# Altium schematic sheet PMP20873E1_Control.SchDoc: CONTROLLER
size 431 x 279 mm; Date: Not shown in title block; ApprovedBy: Not shown in title block; CheckedBy: Not shown in title block; Author: Not shown in title block; CompanyName: Not shown in title block; DrawnBy: Eric Faraci; Engineer: Not shown in title block; Organization: Not shown in title block; Address1: Not shown in title block; Address2: Not shown in title block; Address3: Not shown in title block; Address4: Not shown in title block; DocumentNumber: 3; Revision: Use project parameter SCH_Rev; SheetNumber: 3; SheetTotal: 8; PageSetup: Record=PageOptions¦CenterHorizontal=True¦CenterVertical=True¦PrintScale=0.96¦XCorrection=1.00¦YCorrection=1.00¦PrintKind=0¦BorderSize=5000000¦LeftOffset=0¦BottomOffset=0¦Orientation=2¦PaperLength=1000¦PaperWidth=1000¦Scale=100¦PaperSource=15¦PrintQuality=600¦MediaType=1¦DitherType=10¦PaperKind=11x17¦PrintScaleMode=1
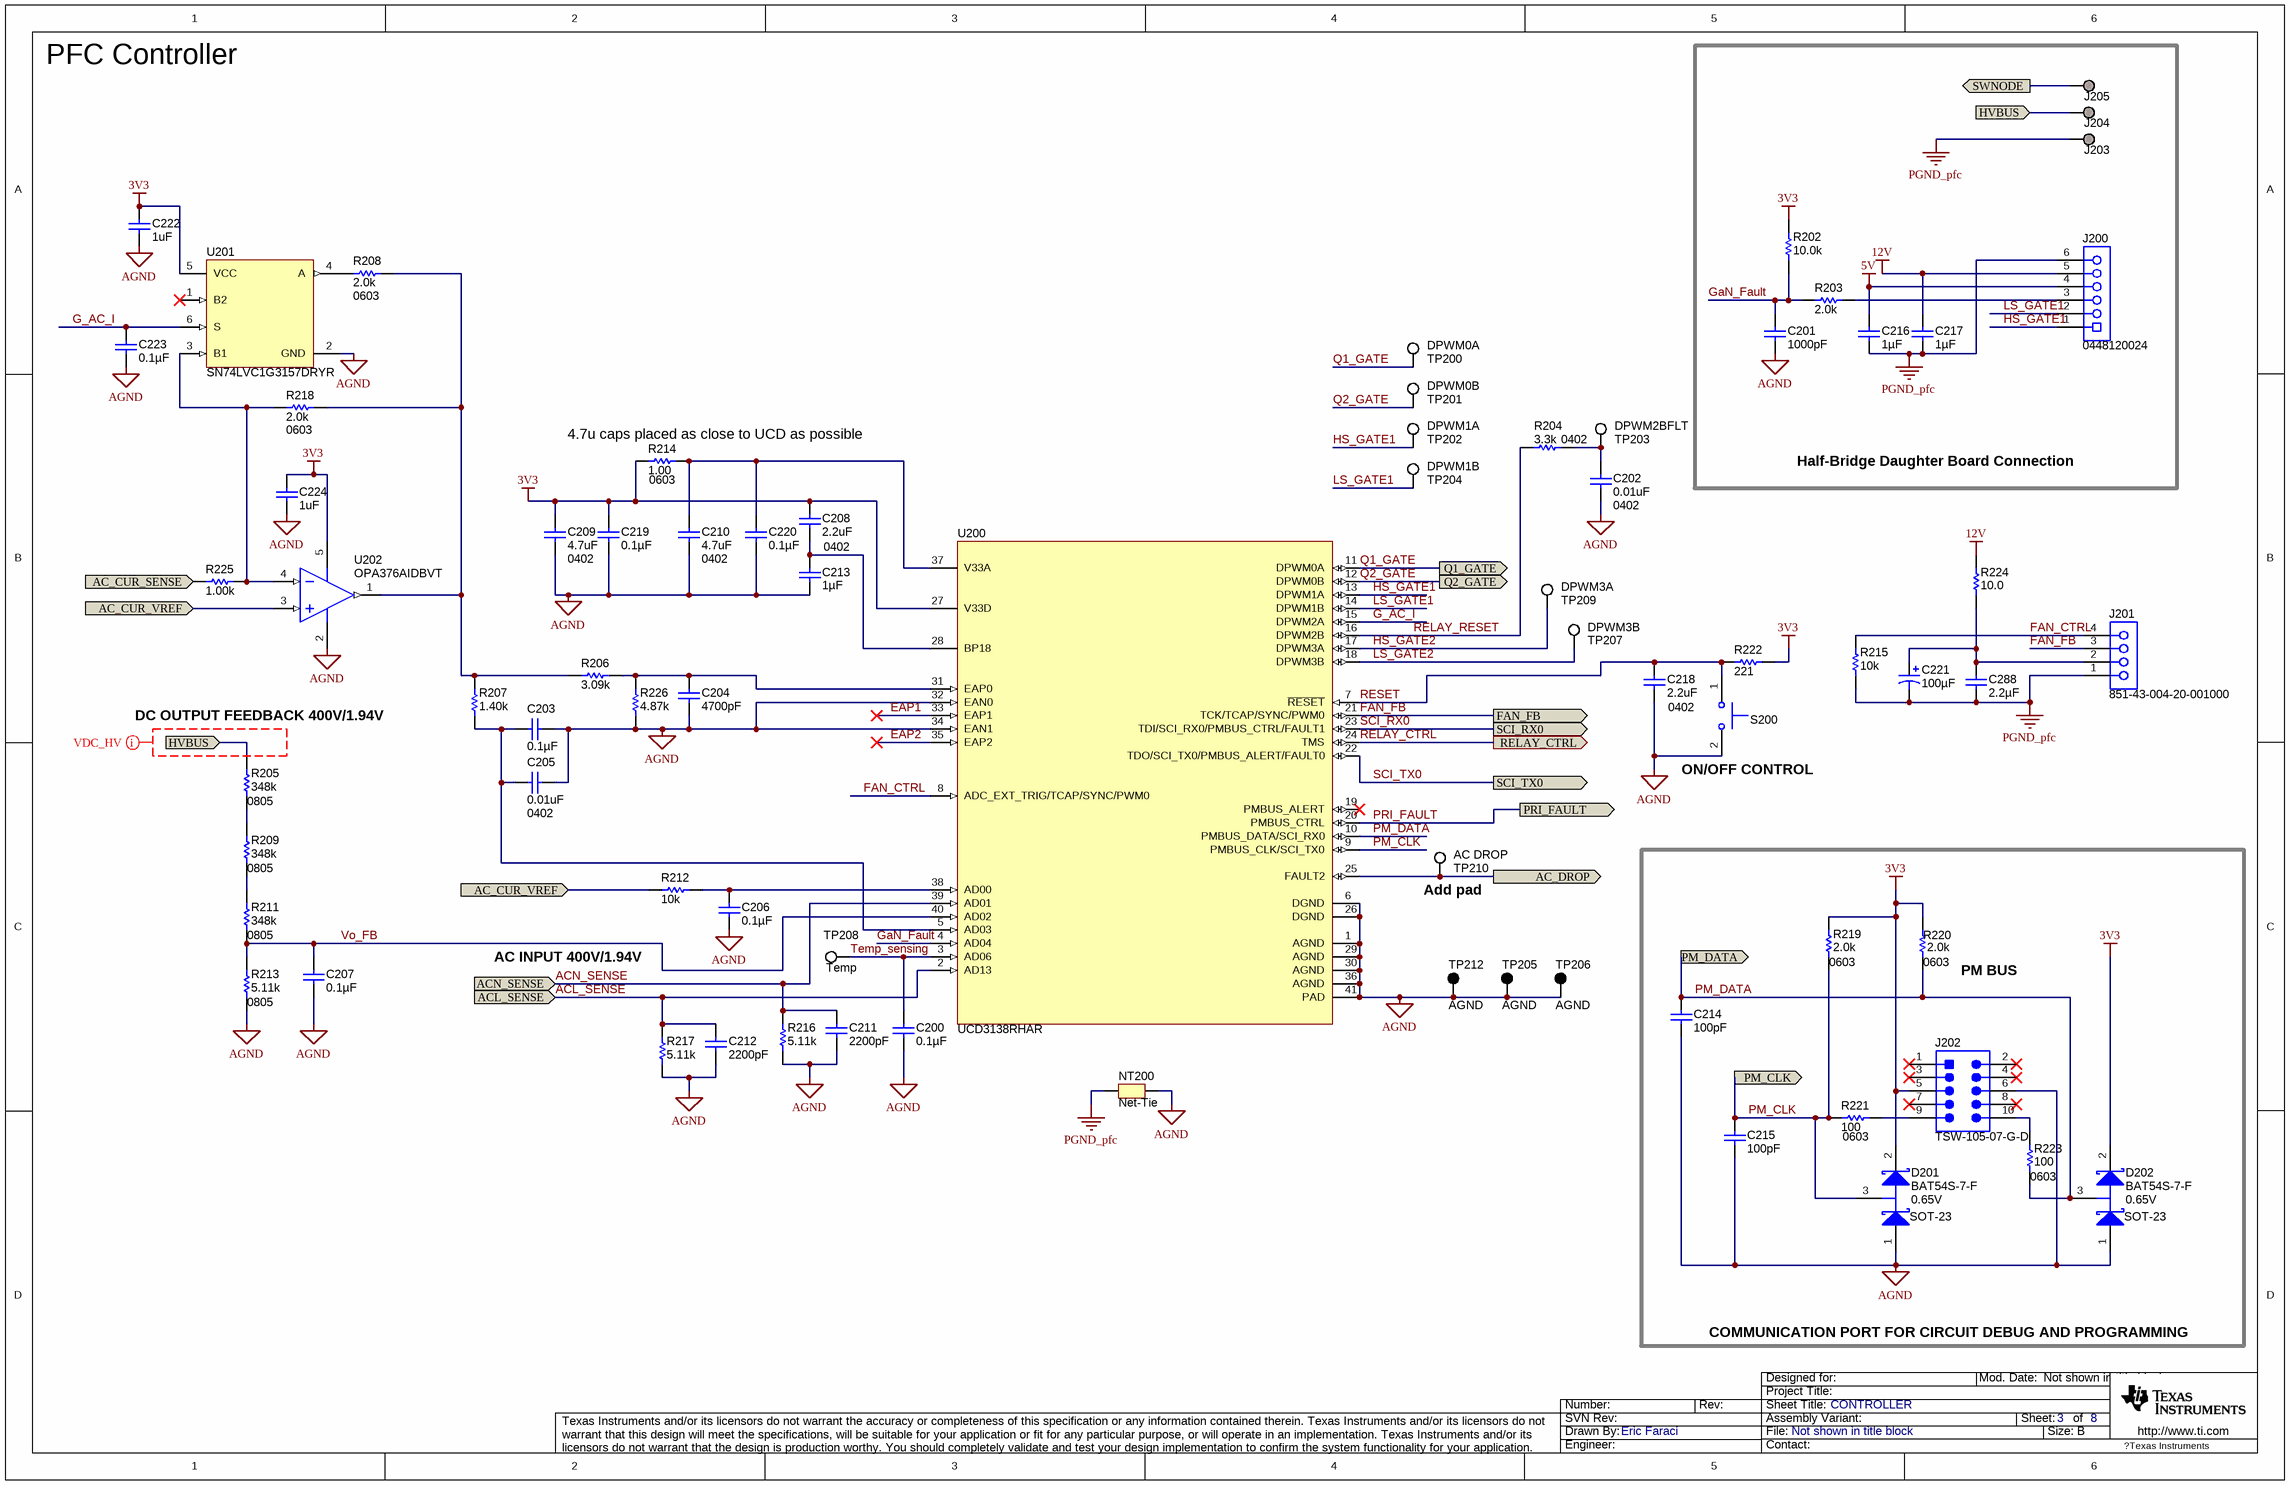
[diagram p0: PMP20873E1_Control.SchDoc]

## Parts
C200  ValueDisplayed: 0.1µF  [0402]  (hidden comment: GRM155R60J104KA01D)
C201  ValueDisplayed: 1000pF  [0402]  (hidden comment: GRM155R61A102KA01D)
C202  ValueDisplayed: 0.01uF  [0402]  (hidden comment: GRM155R70J103KA01D)
C203  ValueDisplayed: 0.1µF  [0402]  (hidden comment: GRM155R60J104KA01D)
C204  ValueDisplayed: 4700pF  [0402]  (hidden comment: GRM155R60J472KA01D)
C205  ValueDisplayed: 0.01uF  [0402]  (hidden comment: GRM155R70J103KA01D)
C206  ValueDisplayed: 0.1µF  [0402]  (hidden comment: GRM155R60J104KA01D)
C207  ValueDisplayed: 0.1µF  [0603]  (hidden comment: GCM188R71H104KA57D)
C208  ValueDisplayed: 2.2uF  [0402]  (hidden comment: C1005X5R1A225K050BC)
C209  value 4.7uF  [0402]  (hidden comment: CL05A475MQ5NRNC)
C210  value 4.7uF  [0402]  (hidden comment: CL05A475MQ5NRNC)
C211  ValueDisplayed: 2200pF  [0603]  (hidden comment: C1608X7R1H222K)
C212  ValueDisplayed: 2200pF  [0603]  (hidden comment: C1608X7R1H222K)
C213  ValueDisplayed: 1µF  [0402]  (hidden comment: GRM155R61A105KE15D)
C214  ValueDisplayed: 100pF  [0402]  (hidden comment: GRM1555C1H101JA01D)
C215  ValueDisplayed: 100pF  [0402]  (hidden comment: GRM1555C1H101JA01D)
C216  ValueDisplayed: 1µF  [0603]  (hidden comment: C1608X7R1E105K080AB)
C217  ValueDisplayed: 1µF  [0603]  (hidden comment: C1608X7R1E105K080AB)
C218  ValueDisplayed: 2.2uF  [0402]  (hidden comment: C1005X5R1A225K050BC)
C219  ValueDisplayed: 0.1µF  [0402]  (hidden comment: GRM155R60J104KA01D)
C220  ValueDisplayed: 0.1µF  [0402]  (hidden comment: GRM155R60J104KA01D)
C221  ValueDisplayed: 100µF  [7343-43]  (hidden comment: T495X107K016ATE100)
C222  ValueDisplayed: 1uF  [0603]  (hidden comment: C1608X7R1E105K080AB)
C223  ValueDisplayed: 0.1µF  [0603]  (hidden comment: GCM188R71H104KA57D)
C224  ValueDisplayed: 1uF  [0603]  (hidden comment: C1608X7R1E105K080AB)
C288  ValueDisplayed: 2.2µF  [1206]  (hidden comment: 12063D225KAT2A)
D201  BAT54S-7-F  value 0.65V  [SOT-23]
D202  BAT54S-7-F  value 0.65V  [SOT-23]
J200  0448120024  [Molex_0448120024]
J201  851-43-004-20-001000  [CONN_851-43-004-20-001000]
J202  TSW-105-07-G-D  [TSW-105-07-G-D]
J203  Suggest using a net name here  [Mill-Max_0312-0-15-15-34-27-10-0]  (value not drawn)
J204  Suggest using a net name here  [Mill-Max_0312-0-15-15-34-27-10-0]  (value not drawn)
J205  Suggest using a net name here  [Mill-Max_0312-0-15-15-34-27-10-0]  (value not drawn)
NT200  Net-Tie  [Net-Tie_50milWide_30milLong]  (net tie, no BOM)
R202  ValueDisplayed: 10.0k  [0402]  (hidden comment: ERJ-2RKF1002X)
R203  value 2.0k  [0402]  (hidden comment: CRCW04022K00JNED)
R204  value 3.3k  [0402]  (hidden comment: CRCW04023K30JNED)
R205  value 348k  PackageReference: 0805  [0805_HV]  (hidden comment: RT0805BRD07348KL)
R206  ValueDisplayed: 3.09k  [0402]  (hidden comment: ERA-2AEB3091X)
R207  value 1.40k  [0402]  (hidden comment: CRCW04021K40FKED)
R208  value 2.0k  [0603]  (hidden comment: CRCW06032K00JNEA)
R209  value 348k  PackageReference: 0805  [0805_HV]  (hidden comment: RT0805BRD07348KL)
R211  value 348k  PackageReference: 0805  [0805_HV]  (hidden comment: RT0805BRD07348KL)
R212  value 10k  [0402]  (hidden comment: CRCW040210K0JNED)
R213  value 5.11k  PackageReference: 0805  [0805_HV]  (hidden comment: RT0805BRD075K11L)
R214  value 1.00  [0603]  (hidden comment: CRCW06031R00FKEA)
R215  value 10k  [0402]  (hidden comment: CRCW040210K0JNED)
R216  ValueDisplayed: 5.11k  [0603]  (hidden comment: RT0603BRD075K11L)
R217  ValueDisplayed: 5.11k  [0603]  (hidden comment: RT0603BRD075K11L)
R218  value 2.0k  [0603]  (hidden comment: CRCW06032K00JNEA)
R219  value 2.0k  [0603]  (hidden comment: CRCW06032K00JNEA)
R220  value 2.0k  [0603]  (hidden comment: CRCW06032K00JNEA)
R221  value 100  [0603]  (hidden comment: CRCW0603100RJNEA)
R222  ValueDisplayed: 221  [0402]  (hidden comment: CRCW0402221RFKED)
R223  value 100  [0603]  (hidden comment: CRCW0603100RJNEA)
R224  ValueDisplayed: 10.0  [1206]  (hidden comment: ERJ-8ENF10R0V)
R225  ValueDisplayed: 1.00k  [0603]  (hidden comment: RC0603FR-071KL)
R226  ValueDisplayed: 4.87k  [0402]  (hidden comment: ERA-2AEB4871X)
S200  SKRKAEE010  [SW_SKRKAEE010]  (value not drawn)
TP200  DPWM0A  [Keystone5002]
TP201  DPWM0B  [Keystone5002]
TP202  DPWM1A  [Keystone5002]
TP203  DPWM2BFLT  [Keystone5002]
TP204  DPWM1B  [Keystone5002]
TP205  AGND  [Keystone5001]
TP206  AGND  [Keystone5001]
TP207  DPWM3B  [Keystone5002]
TP208  Temp  [Keystone5002]
TP209  DPWM3A  [Keystone5002]
TP210  AC DROP  [Keystone5002]
TP212  AGND  [Keystone5001]
U200  UCD3138RHAR  [RHA0040B]
U201  SN74LVC1G3157DRYR  [DRY0006A]
U202  OPA376AIDBVT  [DBV0005A_N]

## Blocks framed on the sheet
Half-Bridge Daughter Board Connection: C201 C216 C217 J200 J203-J205 R202 R203

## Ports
AC_CUR_SENSE, AC_CUR_VREF, AC_DROP, ACL_SENSE, ACN_SENSE, FAN_FB (out), HVBUS, PM_CLK, PM_DATA, PRI_FAULT (out), Q1_GATE (out), Q2_GATE (out), RELAY_CTRL (out), SCI_RX0 (out), SCI_TX0 (out), SWNODE

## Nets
3V3: C208.1 C209.1 C219.1 C222.2 C224.2 D201.2(K) D202.2(K) J202.5 R202.2 R214.2 R219.2 R220.2 R222.2 U200.27(V33D) U201.5(VCC) U202.5(V+)
5V: C216.2 J200.4
12V: C217.2 J200.5 R224.2
AGND: C200.1 C201.2 C202.1 C203.2 C204.2 C205.2 C206.1 C207.2 C209.2 C210.2 C211.2 C212.2 C213.2 C214.2 C215.2 C218.2 C219.2 C220.2 C222.1 C223.2 C224.1 D201.1(A) D202.1(A) J202.6 NT200.2 R213.1 R216.1 R217.1 R226.1 S200.2 TP205.1 TP206.1 TP212.1 U200.1(AGND) U200.6(DGND) U200.26(DGND) U200.29(AGND) U200.30(AGND) U200.32(EAN0) U200.34(EAN1) U200.36(AGND) U200.41(PAD) U201.2(GND) U202.2(V-)
PGND_pfc: C216.1 C217.1 C221.2(-) C288.1 J200.6 J201.1 J203.1 NT200.1 R215.1
AC_CUR_SENSE: R225.1 ; port AC_CUR_SENSE
AC_CUR_VREF: R212.2 U202.3(IN+) ; port AC_CUR_VREF
AC_DROP: TP210.1 U200.25(FAULT2) ; port AC_DROP
ACL_SENSE: C212.1 R217.2 U200.2(AD13) ; port ACL_SENSE
ACN_SENSE: C211.1 R216.2 U200.39(AD01) ; port ACN_SENSE
EAP1: U200.33(EAP1)
EAP2: U200.35(EAP2)
FAN_CTRL: J201.4 R215.2 U200.8(ADC_EXT_TRIG/TCAP/SYNC/PWM0)
FAN_FB: J201.3 U200.21(TCK/TCAP/SYNC/PWM0) ; port FAN_FB
G_AC_I: C223.1 U200.15(DPWM2A) U201.6(S)
GaN_Fault: C201.1 R202.1 R203.1 U200.4(AD04)
HS_GATE1: J200.1 TP202.1 U200.13(DPWM1A)
HS_GATE2: TP209.1 U200.17(DPWM3A)
HVBUS: J204.1 R205.2 ; port HVBUS
LS_GATE1: J200.2 TP204.1 U200.14(DPWM1B)
LS_GATE2: TP207.1 U200.18(DPWM3B)
PM_CLK: C215.1 D201.3(C) R219.1 R221.1 U200.9(PMBUS_CLK/SCI_TX0) ; port PM_CLK
PM_DATA: C214.1 D202.3(C) R220.1 R223.1 U200.10(PMBUS_DATA/SCI_RX0) ; port PM_DATA
PRI_FAULT: U200.20(PMBUS_CTRL) ; port PRI_FAULT
Q1_GATE: TP200.1 U200.11(DPWM0A) ; port Q1_GATE
Q2_GATE: TP201.1 U200.12(DPWM0B) ; port Q2_GATE
RELAY_CTRL: U200.24(TMS) ; port RELAY_CTRL
RELAY_RESET: R204.1 U200.16(DPWM2B)
RESET: C218.1 R222.1 S200.1 U200.7(~{RESET})
SCI_RX0: U200.23(TDI/SCI_RX0/PMBUS_CTRL/FAULT1) ; port SCI_RX0
SCI_TX0: U200.22(TDO/SCI_TX0/PMBUS_ALERT/FAULT0) ; port SCI_TX0
SWNODE: J205.1 ; port SWNODE
Temp_sensing: C200.2 TP208.1 U200.3(AD06)
Vo_FB: C207.1 R211.1 R213.2 U200.40(AD02)
NetC202_2: C202.2 R204.2 TP203.1
NetC203_1: C203.1 C205.1 R207.1 U200.5(AD03)
NetC204_1: C204.1 R206.2 R226.2 U200.31(EAP0)
NetC206_2: C206.2 R212.1 U200.38(AD00)
NetC208_2: C208.2 C213.1 U200.28(BP18)
NetC210_1: C210.1 C220.1 R214.1 U200.37(V33A)
NetC221_1: C221.1(+) C288.2 J201.2 R224.1
NetJ200_3: J200.3 R203.2
NetJ202_9: J202.9 R221.2
NetJ202_10: J202.10 R223.2
NetR205_1: R205.1 R209.2
NetR206_1: R206.1 R207.2 R208.1 R218.1 U202.1(OUT)
NetR208_2: R208.2 U201.4(A)
NetR209_1: R209.1 R211.2
NetR218_2: R218.2 R225.2 U201.3(B1) U202.4(IN-)

Not connected (* = marked no-connect by the designer): J202 1* 2* 3* 4* 7* 8*; U200 19(PMBUS_ALERT)*; U201 1(B2)*

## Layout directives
net class VDC_HV: (no net found under the mark)

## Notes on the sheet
- PFC Controller
- (near R214) 4.7u caps placed as close to UCD as possible
- (near R205) DC OUTPUT FEEDBACK 400V/1.94V
- (near S200) ON/OFF CONTROL
- (near TP210) Add pad
- AC INPUT 400V/1.94V
- (near R220) PM BUS
- COMMUNICATION PORT FOR CIRCUIT DEBUG AND PROGRAMMING

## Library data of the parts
C200 C203 C206 C219 C220 = GRM155R60J104KA01D: CAP, CERM, 0.1uF, 6.3V, +/-10%, X5R, 0402; Manufacturer: MuRata; Polarized: N; CompType: Capacitor; U/M: EA; Cap_F: 0.0000001; Tolerance_%: 10; Value1: Unknown; VDC_V: 6.3; TaMin_C: -55; TaMax_C: 85
C201 = GRM155R61A102KA01D: CAP, CERM, 1000pF, 10V, +/-10%, X5R, 0402; Manufacturer: MuRata; Polarized: N; CompType: Capacitor; U/M: EA; Cap_F: 0.000000001; Tolerance_%: 10; Value1: Unknown; TaMin_C: -55; TaMax_C: 85
C202 C205 = GRM155R70J103KA01D: CAP, CERM, 0.01uF, 6.3V, +/-10%, X7R, 0402; Manufacturer: MuRata; Polarized: N; CompType: Capacitor; U/M: EA; Cap_F: 0.00000001; Tolerance_%: 10; Value1: Unknown; VDC_V: 6.3; TaMin_C: -55; TaMax_C: 125
C204 = GRM155R60J472KA01D: CAP, CERM, 4700pF, 6.3V, +/-10%, X5R, 0402; Manufacturer: MuRata; Polarized: N; CompType: Capacitor; U/M: EA; Cap_F: 0.0000000047; Tolerance_%: 10; Value1: Unknown; VDC_V: 6.3; TaMin_C: -55; TaMax_C: 85
C207 C223 = GCM188R71H104KA57D: CAP, CERM, 0.1 µF, 50 V, +/- 10%, X7R, 0603; Manufacturer: MuRata; Polarized: N; CompType: Capacitor; Value: 0.1uF; U/M: EA; Cap_F: 0.0000001; Tolerance_%: 10; ESR_ohm: 0.02; Value1: 0.02 ohm; VDC_V: 50; Value2: 50V; IRMS_A: 1.84; TaMin_C: -55; TaMax_C: 125; AEC Category: Q200
C208 C218 = C1005X5R1A225K050BC: CAP, CERM, 2.2uF, 10V, +/-10%, X5R, 0402; Manufacturer: TDK; Polarized: N; CompType: Capacitor; U/M: EA; Cap_F: 0.0000022; Tolerance_%: 10; Value1: Unknown; TaMin_C: -55; TaMax_C: 85
C209 C210 = Capacitor: CAP, CER, 4.7UF, 6.3V, 20%, X5R, 0402; Manufacturer: Samsung Electro-Mechanics America; Polarized: N; U/M: EA; Tolerance_%: ?0%
C211 C212 = C1608X7R1H222K: CAP, CERM, 2200 pF, 50 V, +/- 10%, X7R, 0603; Manufacturer: TDK; Polarized: N; CompType: Capacitor; Value: 2200pF; U/M: EA; Cap_F: 0.0000000022; Tolerance_%: 10; ESR_ohm: 0.145; Value1: 0.145 ohm; VDC_V: 50; Value2: 50V; TaMin_C: -55; TaMax_C: 125; AEC Category: Q200
C213 = GRM155R61A105KE15D: CAP, CERM, 1uF, 10V, +/-10%, X5R, 0402; Manufacturer: MuRata; Polarized: N; CompType: Capacitor; U/M: EA; Cap_F: 0.000001; Tolerance_%: 10; Value1: Unknown; TaMin_C: -55; TaMax_C: 85
C214 C215 = GRM1555C1H101JA01D: CAP, CERM, 100pF, 50V, +/-5%, C0G/NP0, 0402; Manufacturer: MuRata; Polarized: N; CompType: Capacitor; U/M: EA; Cap_F: 0.0000000001; Tolerance_%: 5; Value1: Unknown; VDC_V: 50; TaMin_C: -55; TaMax_C: 125
C216 C217 = C1608X7R1E105K080AB: CAP, CERM, 1 µF, 25 V, +/- 10%, X7R, 0603; Manufacturer: TDK; Polarized: N; CompType: Capacitor; Value: 1uF; U/M: EA; Cap_F: 0.000001; Tolerance_%: 10; Value1: Unknown; VDC_V: 25; Value2: 25V; TaMin_C: -55; TaMax_C: 125
C221 = T495X107K016ATE100: CAP, TA, 100 µF, 16 V, +/- 10%, 0.1 ohm, SMD; Manufacturer: Kemet; Polarized: Y; CompType: Capacitor; Value: 100uF; U/M: EA; Cap_F: 0.0001; Tolerance_%: 10; Value1: 0.1 ohm; VDC_V: 16; Value2: 16V; ESR_ohm: 0.1; IRMS_A: 1.156; TaMin_C: -55; TaMax_C: 125; Cap_Case: X; AEC Category: Q200
C222 C224 = C1608X7R1E105K080AB: CAP, CERM, 1uF, 25V, +/-10%, X7R, 0603; Manufacturer: TDK; Polarized: N; CompType: Capacitor; U/M: EA; Cap_F: 0.000001; Tolerance_%: 10; Value1: Unknown; VDC_V: 25; TaMin_C: -55; TaMax_C: 125
C288 = 12063D225KAT2A: CAP, CERM, 2.2 µF, 25 V, +/- 10%, X5R, 1206; Manufacturer: AVX; Polarized: N; CompType: Capacitor; Value: 2.2uF; U/M: EA; Cap_F: 0.0000022; Tolerance_%: 10; ESR_ohm: 0.016; Value1: 0.016 ohm; VDC_V: 25; Value2: 25V; TaMin_C: -55; TaMax_C: 85
D201 D202 = BAT54S-7-F: Diode, Schottky, 30V, 0.2A, SOT-23; Manufacturer: Diodes Inc.; U/M: EA; Vf_V: 0.65; Io_A: 0.2; Vr_V: 30; TJmax_C: 125
J200 = 0448120024: Receptacle, 2.54mm, 6x1, Gold, TH; Manufacturer: Molex; SymbolCreator: a0411947; U/M: EA
J201 = 851-43-004-20-001000: SOCKET .050" GRID SIP 4 POS R/A, TH; Manufacturer: Mill-Max; SymbolCreator: a0411947; CompType: Header; U/M: EA
J202 = TSW-105-07-G-D: Header, 100mil, 5x2, Gold, TH; Manufacturer: Samtec; SymbolCreator: a0412235; U/M: EA
J203-J205 = 0312-0-15-15-34-27-10-0: Pin Receptacle, .032-.046" .075" Dia, Gold, TH; Manufacturer: Mill-Max; U/M: EA
NT200 = Net-Tie: Single point connection between nets.; SymbolCreator: codlsc
R202 = ERJ-2RKF1002X: RES, 10.0 k, 1%, 0.1 W, 0402; Manufacturer: Panasonic; CompType: Resistor; Value: 10.0k; Res_ohm: 10000; Value_Code: 10k0; Tolerance_%: 1; Power_W: 0.1; Value2: 0.1W; VDC_V: 50; TempCo: 100 ppm/C; EIA_Code: E96; U/M: EA; AEC Category: Q200
R203 = CRCW04022K00JNED: RES, 2.0k ohm, 5%, 0.063W, 0402; Manufacturer: Vishay-Dale; CompType: Resistor; Res_ohm: 2000; Value_Code: 2k00; Tolerance_%: 5; Power_W: 0.063; VDC_V: 50; TempCo: 200 ppm/C; EIA_Code: E24; U/M: EA
R204 = CRCW04023K30JNED: RES, 3.3k ohm, 5%, 0.063W, 0402; Manufacturer: Vishay-Dale; CompType: Resistor; Res_ohm: 3300; Value_Code: 3k30; Tolerance_%: 5; Power_W: 0.063; VDC_V: 50; TempCo: 200 ppm/C; EIA_Code: E24; U/M: EA
R205 R209 R211 = RT0805BRD07348KL: RES, 348k ohm, 0.1%, 0.125W, 0805; Manufacturer: Yageo America; CompType: Resistor; Res_ohm: 348000; Tolerance_%: 0.1; Power_W: 0.125; VDC_V: 150; TempCo: 25 ppm/C; EIA_Code: E192; U/M: EA
R206 = ERA-2AEB3091X: RES, 3.09 k, 0.1%, 0.062 W, AEC-Q200 Grade 0, 0402; Manufacturer: Panasonic; CompType: Resistor; Value: 3.09k; Res_ohm: 3090; Value_Code: 3k09; Tolerance_%: 0.1; Power_W: 0.062; Value2: 0.062W; VDC_V: 25; TempCo: 25 ppm/C; EIA_Code: E192; U/M: EA; AEC Category: Q200; AEC Qualified: Y; AEC Grade: 0
R207 = CRCW04021K40FKED: RES, 1.40k ohm, 1%, 0.063W, 0402; Manufacturer: Vishay-Dale; CompType: Resistor; Res_ohm: 1400; Value_Code: 1k40; Tolerance_%: 1; Power_W: 0.063; VDC_V: 50; TempCo: 100 ppm/C; EIA_Code: E96; U/M: EA
R208 R218-R220 = CRCW06032K00JNEA: RES, 2.0k ohm, 5%, 0.1W, 0603; Manufacturer: Vishay-Dale; CompType: Resistor; Res_ohm: 2000; Value_Code: 2k00; Tolerance_%: 5; Power_W: 0.1; VDC_V: 75; TempCo: 200 ppm/C; EIA_Code: E24; U/M: EA
R212 R215 = CRCW040210K0JNED: RES, 10k ohm, 5%, 0.063W, 0402; Manufacturer: Vishay-Dale; CompType: Resistor; Res_ohm: 10000; Value_Code: 10k0; Tolerance_%: 5; Power_W: 0.063; VDC_V: 50; TempCo: 200 ppm/C; EIA_Code: E24; U/M: EA
R213 = RT0805BRD075K11L: RES, 5.11k ohm, 0.1%, 0.125W, 0805; Manufacturer: Yageo America; CompType: Resistor; Res_ohm: 5110; Value_Code: 5k11; Tolerance_%: 0.1; Power_W: 0.125; VDC_V: 150; TempCo: 25 ppm/C; EIA_Code: E192; U/M: EA
R214 = CRCW06031R00FKEA: RES, 1.00 ohm, 1%, 0.1W, 0603; Manufacturer: Vishay-Dale; CompType: Resistor; Res_ohm: 1; Value_Code: 1R00; Power_W: 0.1; VDC_V: 75; TempCo: 100 ppm/C; EIA_Code: E96; U/M: EA
R216 R217 = RT0603BRD075K11L: RES, 5.11 k, 0.1%, 0.1 W, 0603; Manufacturer: Yageo America; CompType: Resistor; Value: 5.11k; Res_ohm: 5110; Value_Code: 5k11; Tolerance_%: 0.1; Value2: 0.1W; VDC_V: 75; TempCo: 25 ppm/C; EIA_Code: E192; U/M: EA; AEC Category: Q200
R221 R223 = CRCW0603100RJNEA: RES, 100 ohm, 5%, 0.1W, 0603; Manufacturer: Vishay-Dale; CompType: Resistor; Value_Code: 100R; Tolerance_%: 5; Power_W: 0.1; VDC_V: 75; TempCo: 200 ppm/C; EIA_Code: E24; U/M: EA
R222 = CRCW0402221RFKED: RES, 221, 1%, 0.063 W, 0402; Manufacturer: Vishay-Dale; CompType: Resistor; Value: 221; Value_Code: 221R; Tolerance_%: 1; Power_W: 0.063; Value2: 0.063W; VDC_V: 50; TempCo: 100 ppm/C; EIA_Code: E96; U/M: EA; AEC Category: Q200
R224 = ERJ-8ENF10R0V: RES, 10.0, 1%, 0.25 W, 1206; Manufacturer: Panasonic; CompType: Resistor; Value: 10.0; Res_ohm: 10; Value_Code: 10R0; Tolerance_%: 1; Power_W: 0.25; Value2: 0.25W; VDC_V: 200; TempCo: 100 ppm/C; EIA_Code: E96; U/M: EA; AEC Category: Q200
R225 = RC0603FR-071KL: RES, 1.00 k, 1%, 0.1 W, 0603; Manufacturer: Yageo America; CompType: Resistor; Value: 1.00k; Res_ohm: 1000; Value_Code: 1k00; Tolerance_%: 1; Power_W: 0.1; Value2: 0.1W; VDC_V: 150; TempCo: 200 ppm/C; EIA_Code: E96; U/M: EA; AEC Category: Q200
R226 = ERA-2AEB4871X: RES, 4.87 k, 0.1%, 0.062 W, AEC-Q200 Grade 0, 0402; Manufacturer: Panasonic; CompType: Resistor; Value: 4.87k; Res_ohm: 4870; Value_Code: 4k87; Tolerance_%: 0.1; Power_W: 0.062; Value2: 0.062W; VDC_V: 25; TempCo: 25 ppm/C; EIA_Code: E192; U/M: EA; AEC Category: Q200; AEC Qualified: Y; AEC Grade: 0
S200 = SKRKAEE010: Switch, Push Button, SMD; Manufacturer: Alps; SymbolCreator: a0412235; Circuit: SPST-NO; VDC_V: 12; SwitchFunction: Off-Mom; PositionCount: 1; CurrentRating_mA: 50
TP200-TP204 TP207-TP210 = 5002: Test Point, Miniature, White, TH; Manufacturer: Keystone; CompType: Test Point Loop; U/M: EA
TP205 TP206 TP212 = 5001: Test Point, Miniature, Black, TH; Manufacturer: Keystone; CompType: Test Point Loop; U/M: EA
U200 = UCD3138RHAR: Highly Integrated Digital Controller for Isolated Power, RHA0040B; Alternate PartNumber: UCD3138RHAT; Manufacturer: Texas Instruments; SymbolCreator: Altium; CompType: IC; U/M: EA
U201 = SN74LVC1G3157DRYR: SINGLE-POLE DOUBLE-THROW ANALOG SWITCH, DRY0006A; Manufacturer: Texas Instruments; SymbolCreator: a0799628; CompType: IC; U/M: EA
U202 = OPA376AIDBVT: Precision, Low Noise, Low Iq Operational Amplifier, 2.2 to 5.5 V, -40 to 125 degC, 5-pin SOT23 (DBV0005A), Green (RoHS & no Sb/Br); Manufacturer: Texas Instruments; Alternate PartNumber: Equivalent; CMRR(Min)(dB): 76; IIB(Max)(pA): 10; Iq per channel(Max)(mA): 0.95; Number of Channels: 1; Offset Drift(Typ)(uV/C): 0.32; Slew Rate(Typ)(V/us): 2; Sub Family: Low Input Bias Current Amp (<=10pA), Low Noise Amp (<=10nV/rtHz), Low Offset Voltage Amplifier (<=500uV), Low Supply Voltage Amplifier (<=2.7V), Precision Amplifier; Total Supply Voltage(Max)(+5V is 5, +/-5V is 10): 5.5; Total Supply Voltage(Min)(+5V is 5, +/-5V is 10): 2.2; Vio (25C)(Max)(mV): 0.025; Vn at 1kHz(Typ)(nV/rtHz): 7.5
